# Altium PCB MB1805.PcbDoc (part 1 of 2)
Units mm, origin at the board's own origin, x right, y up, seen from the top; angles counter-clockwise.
Board outline 43 x 47.02 mm, 4 copper layers (Top Layer, Internal 1, Internal 2, Bottom Layer), stack 1.565 mm thick; 110 components, 91 nets, 377 pads, 610 vias.
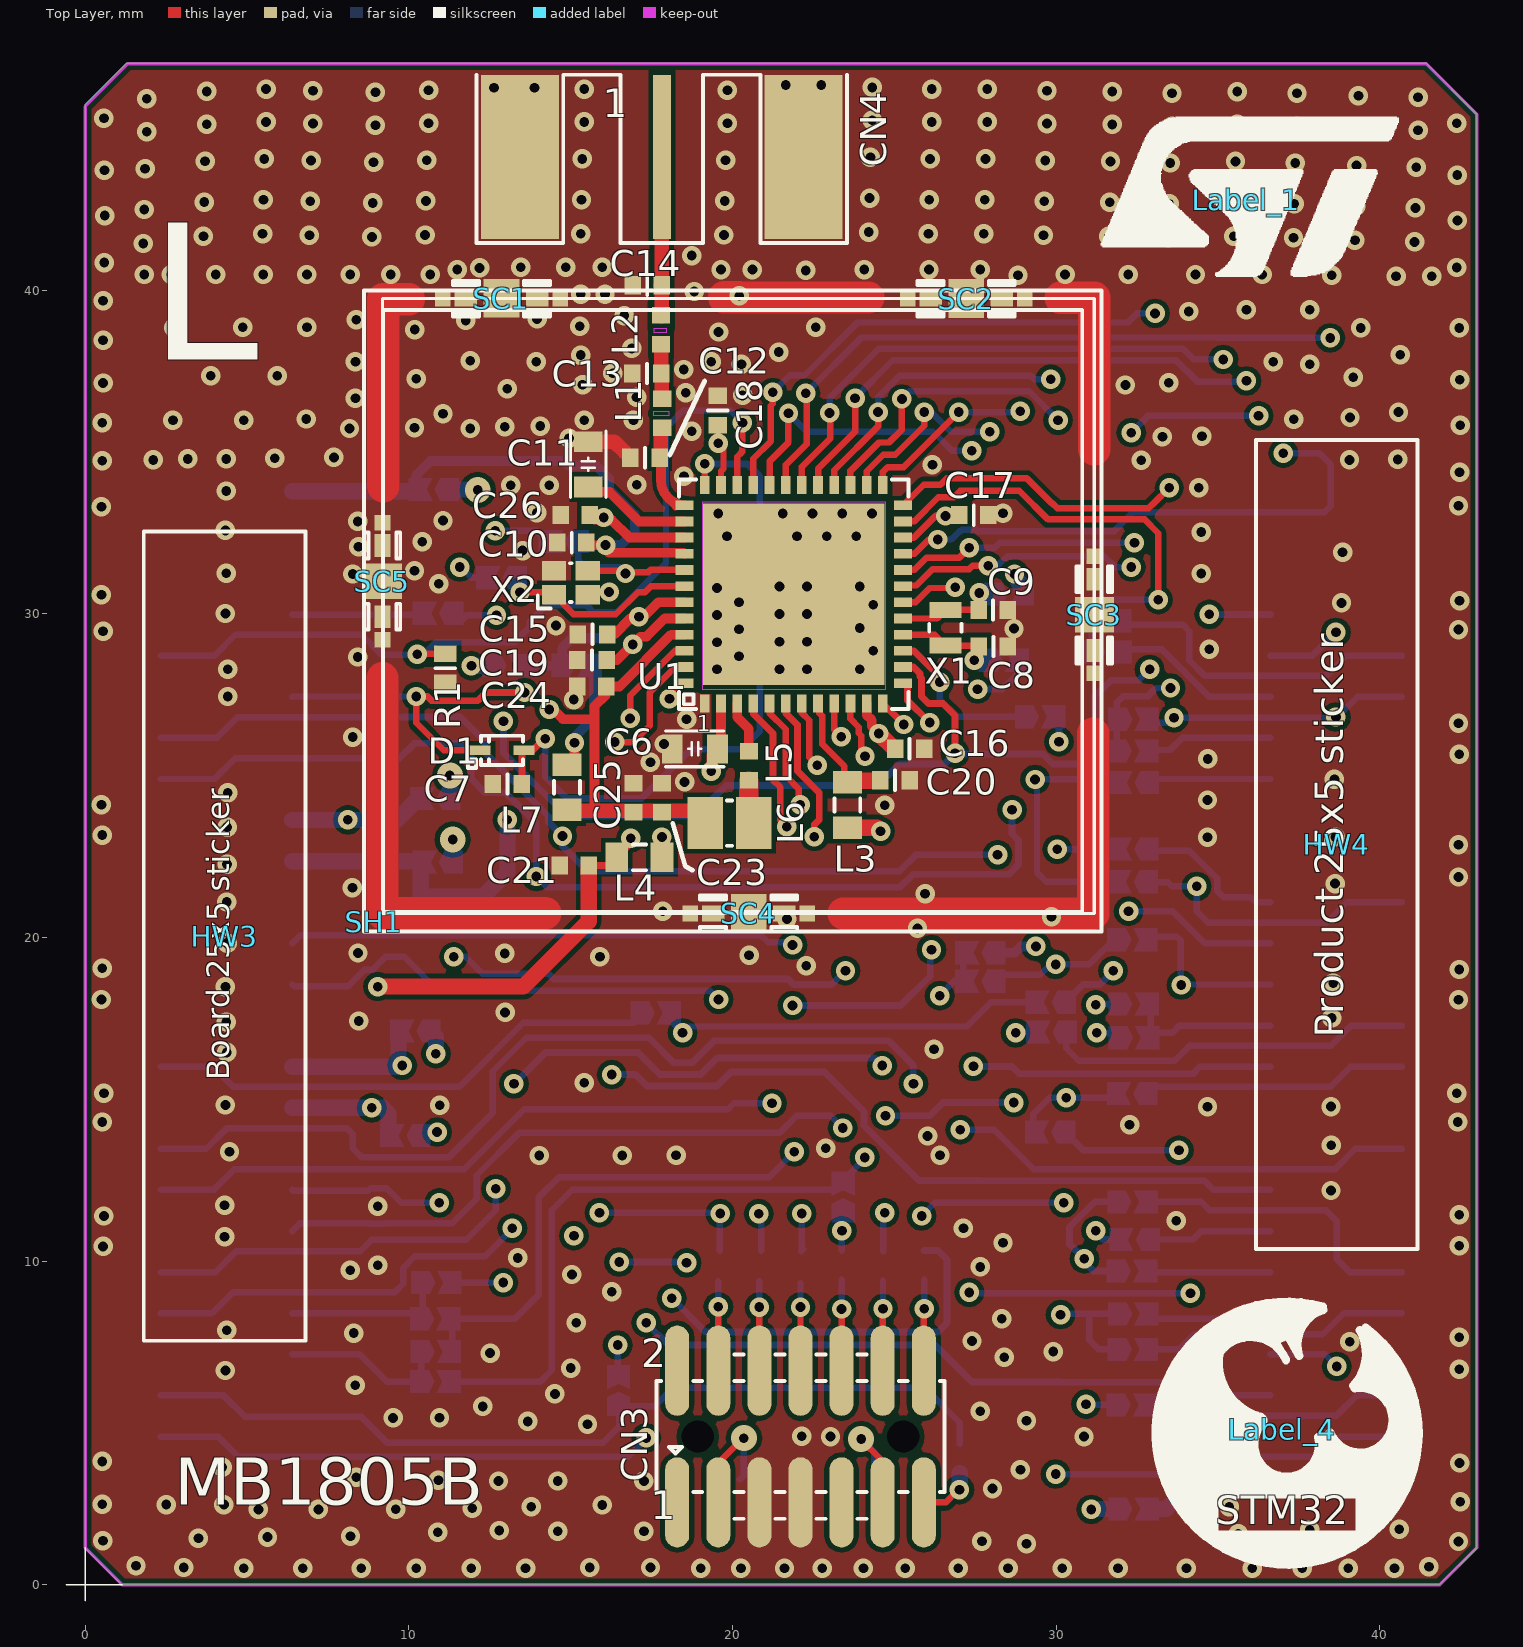
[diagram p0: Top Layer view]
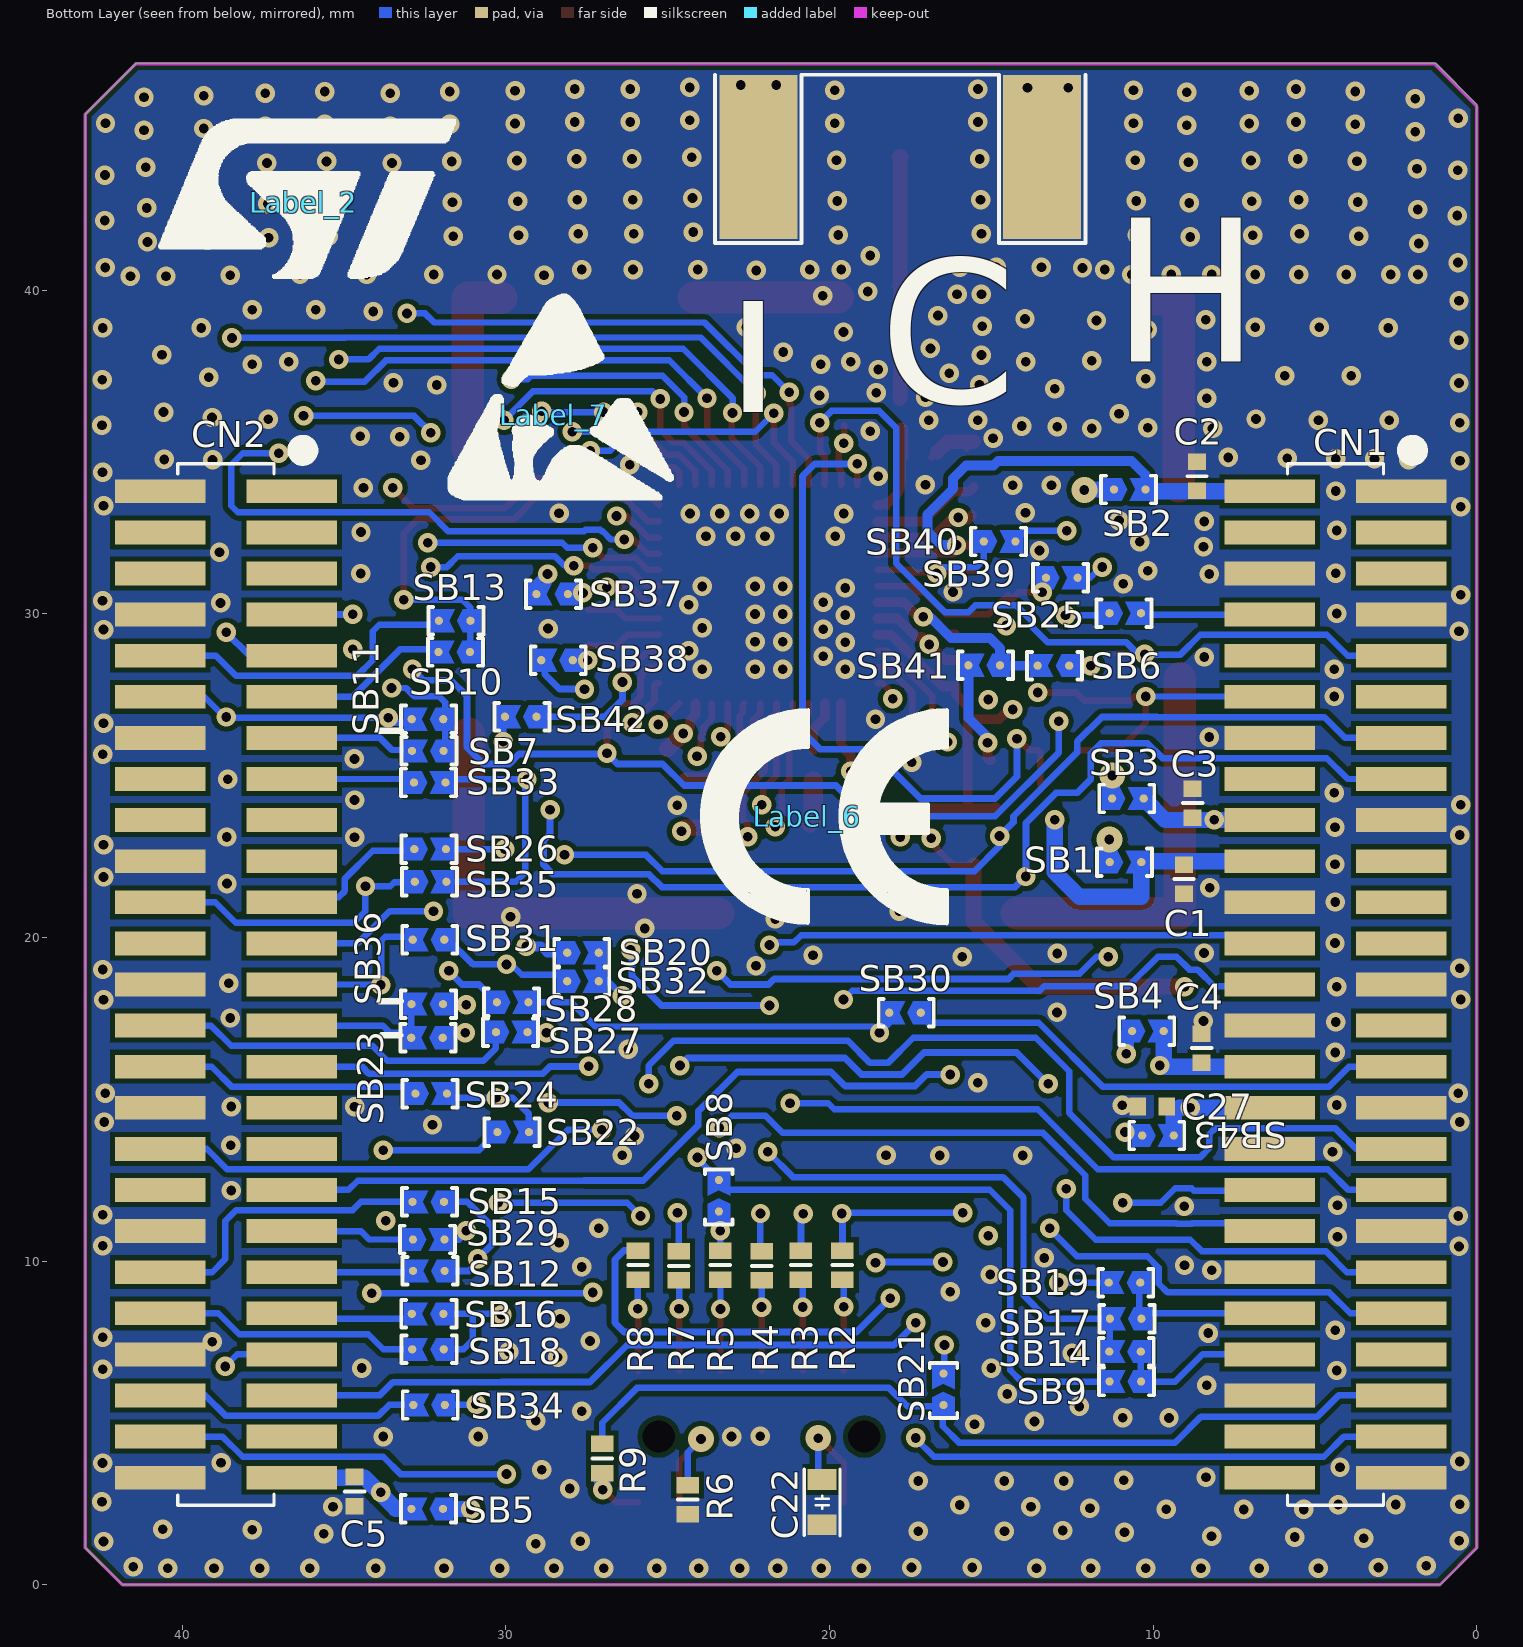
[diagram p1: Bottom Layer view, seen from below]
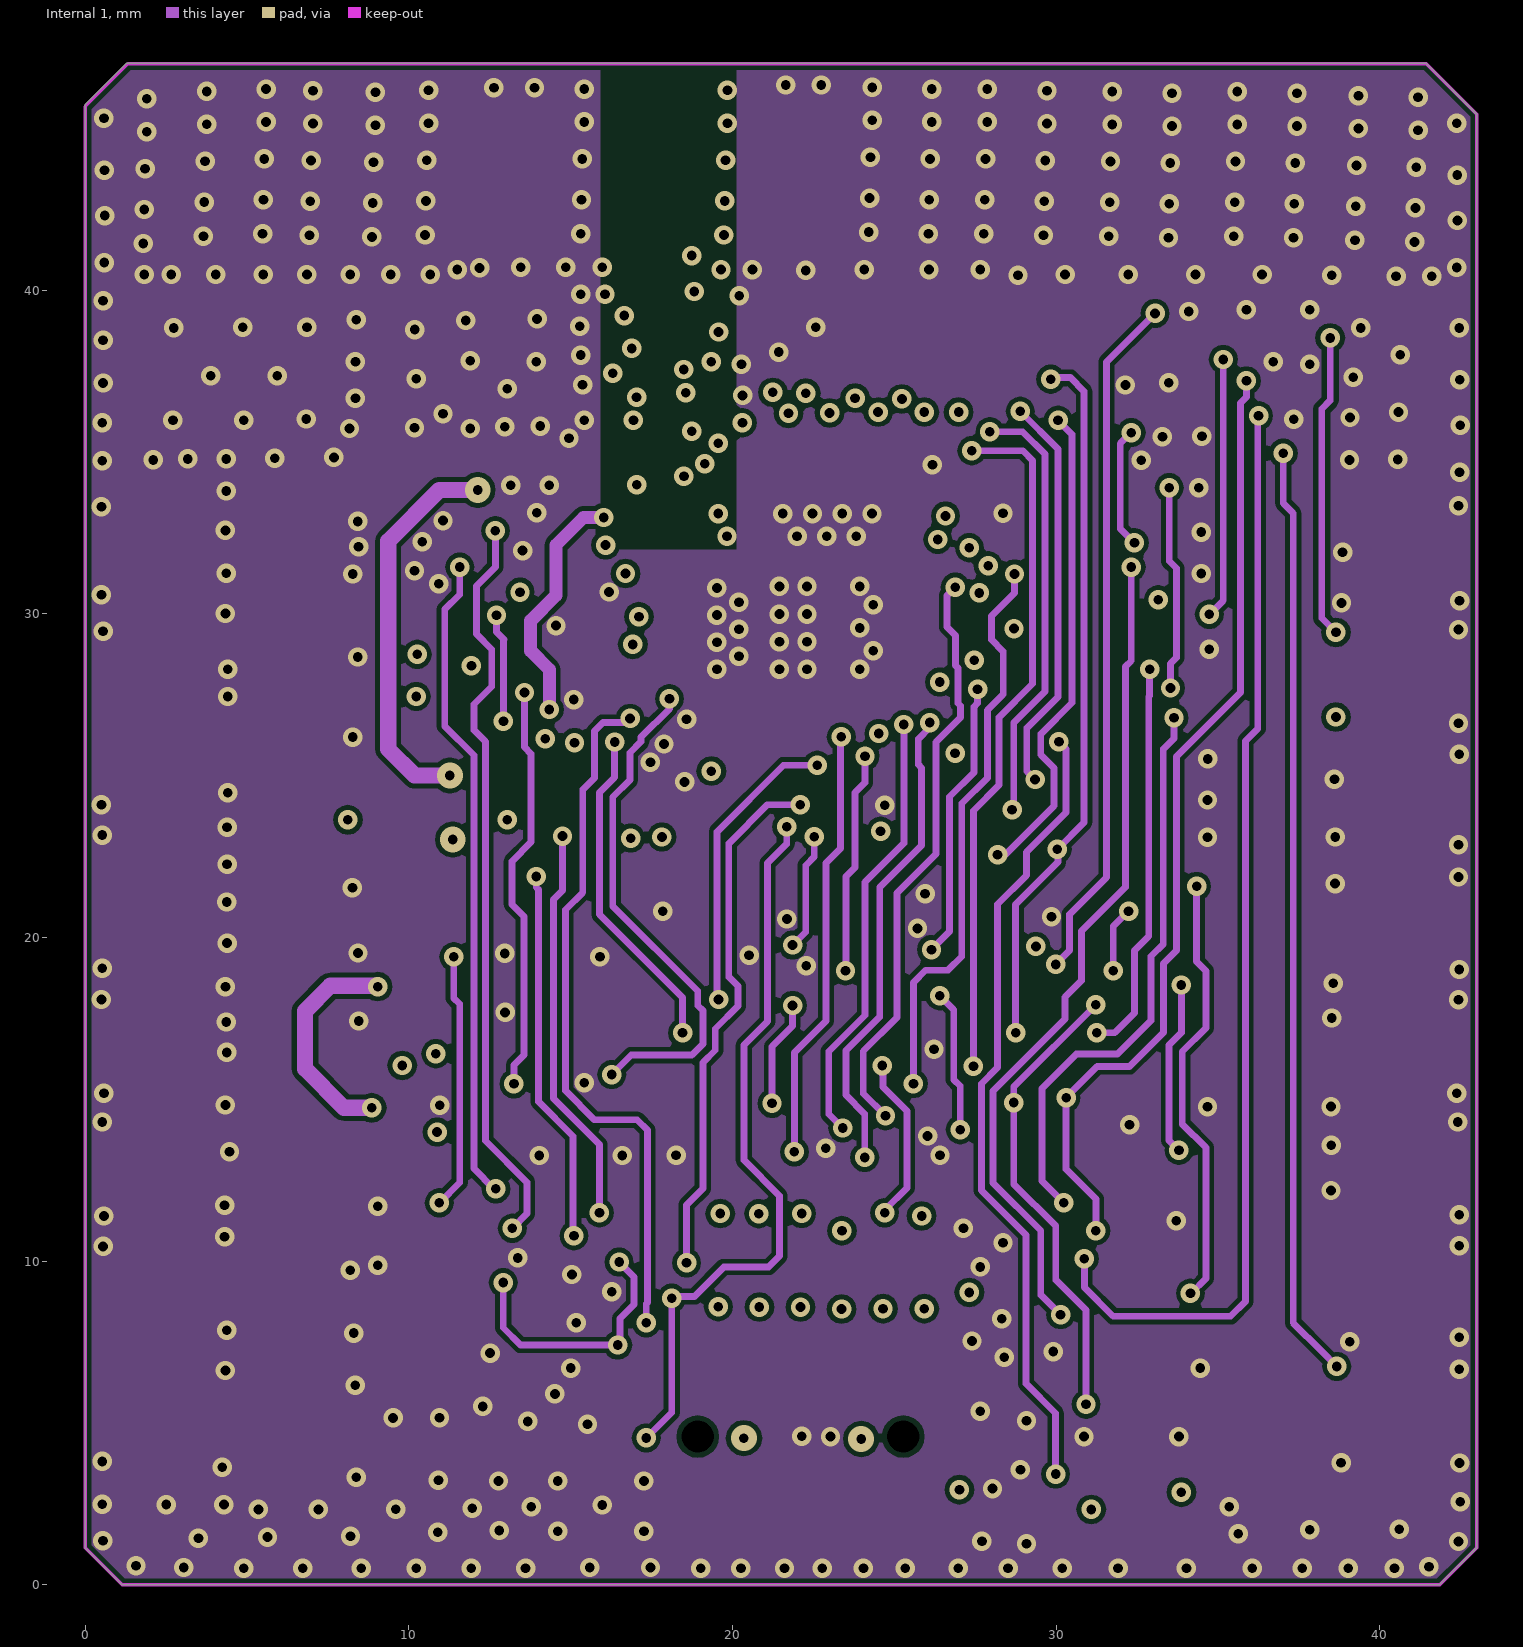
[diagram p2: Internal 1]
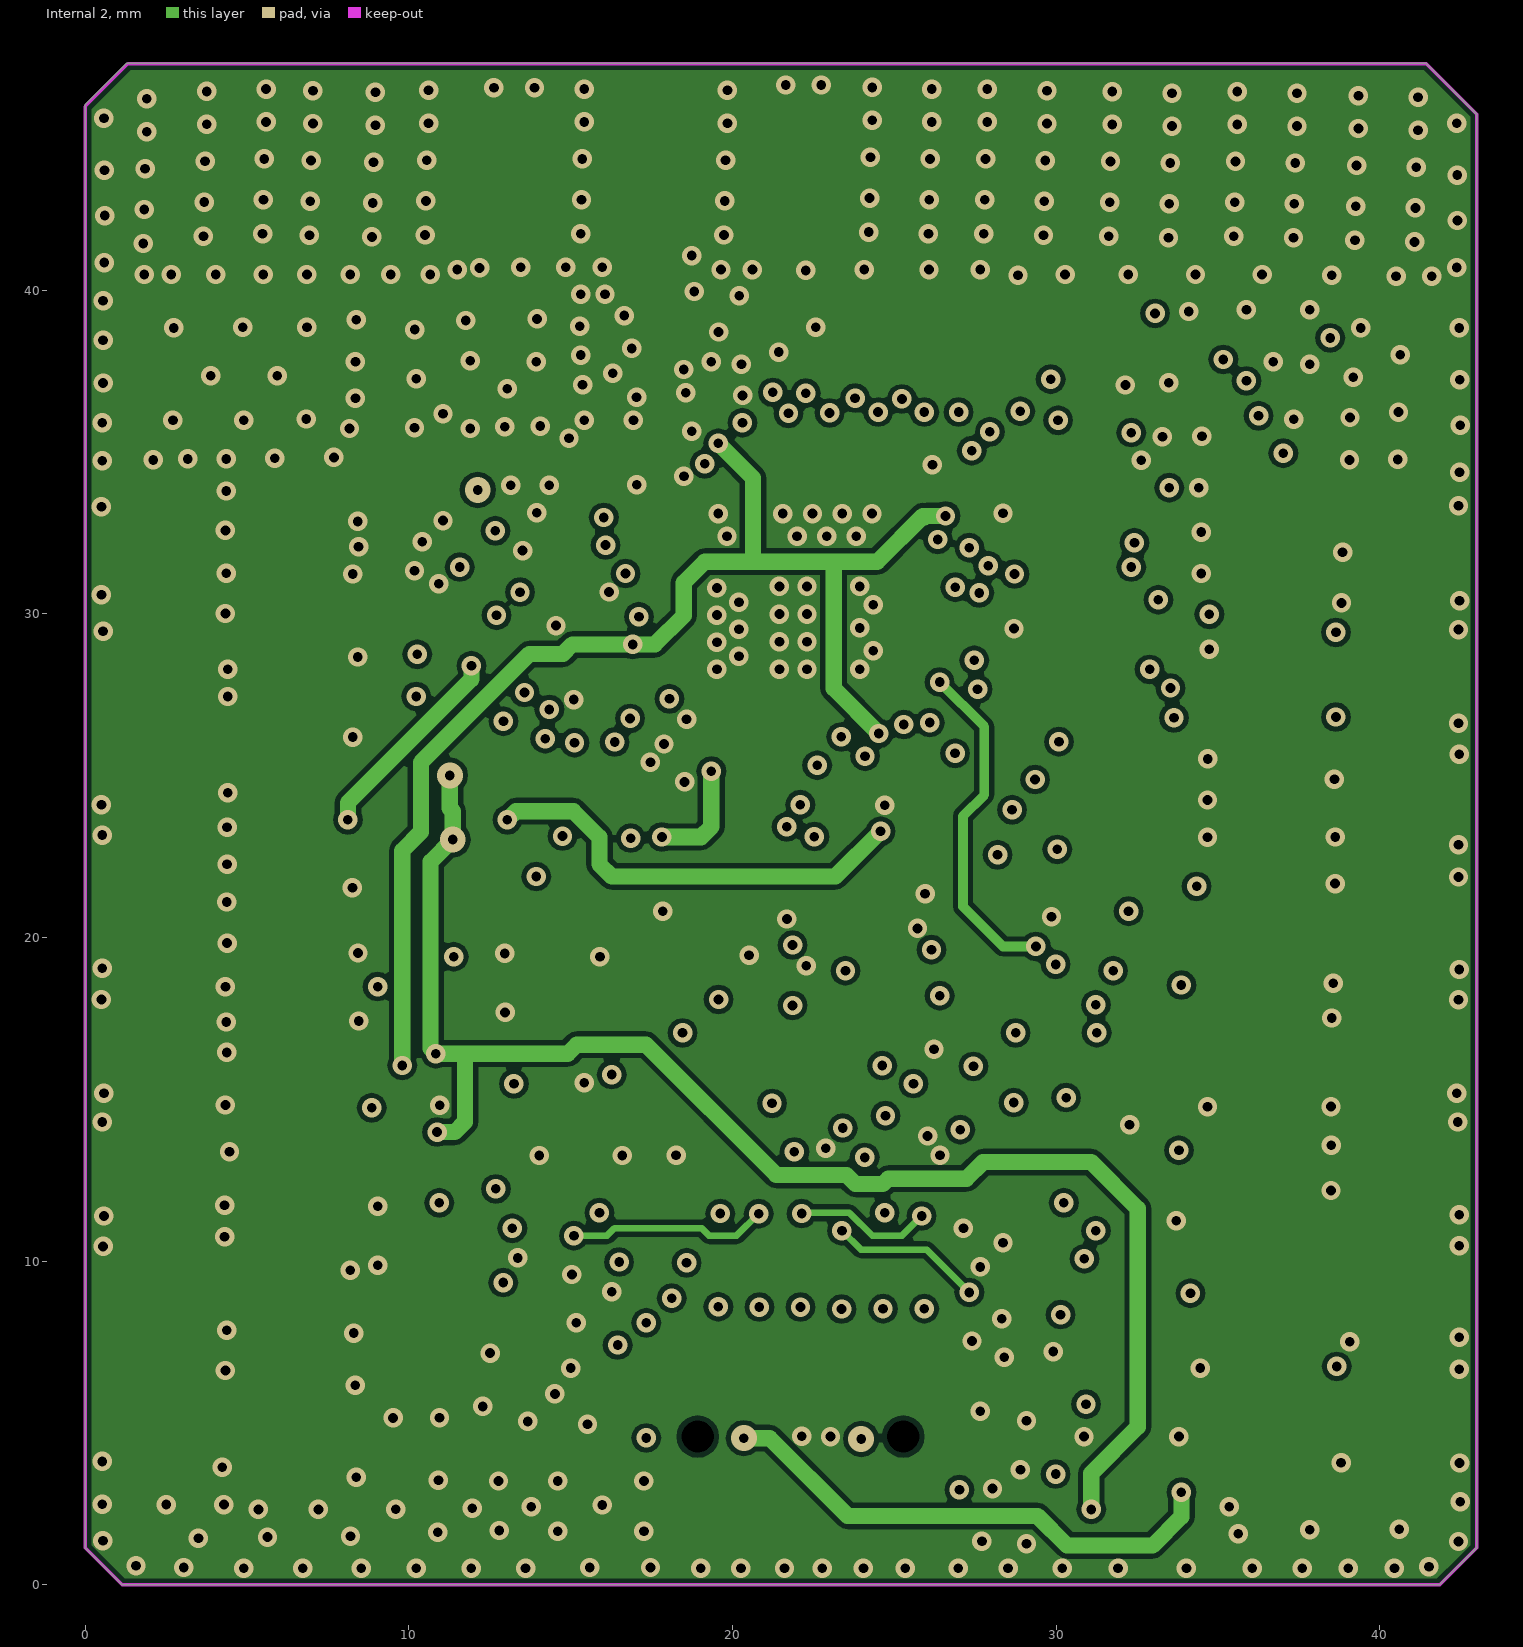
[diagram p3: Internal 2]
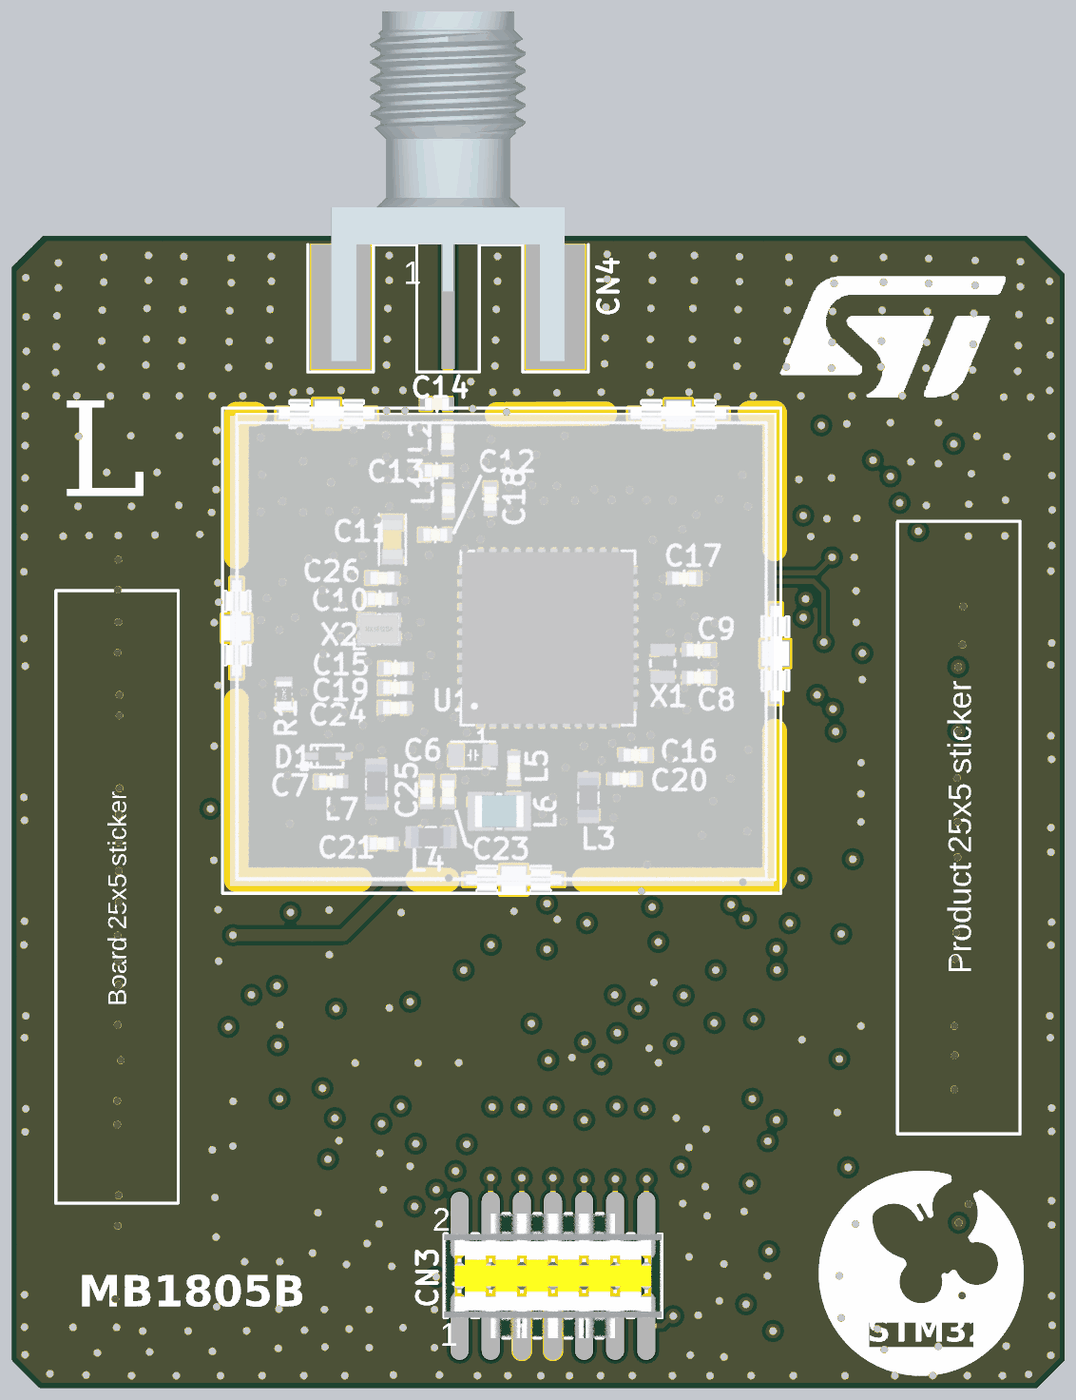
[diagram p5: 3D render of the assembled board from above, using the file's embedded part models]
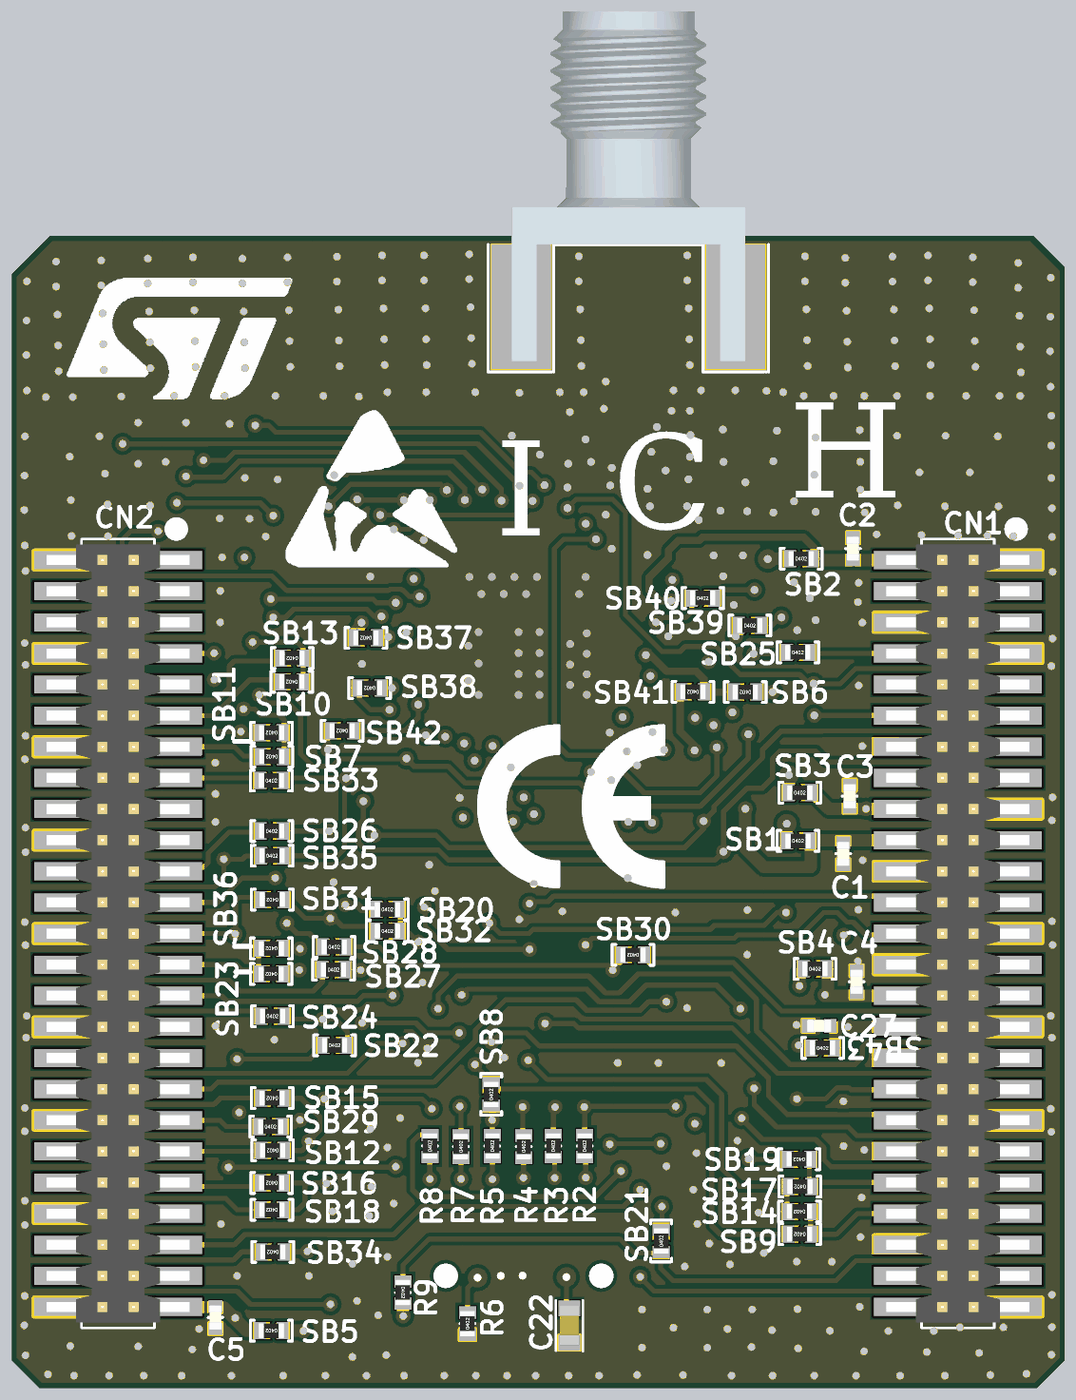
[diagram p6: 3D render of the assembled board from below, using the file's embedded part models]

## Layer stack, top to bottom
Top Solder: solder mask 0.0178, Solder Resist, Dk 4.2
Top Layer: signal copper 0.0406
Dielectric 1: core 0.0762, FR-4, Dk 3.7
Internal 1: signal copper 0.0305
Dielectric 3: prepreg 1.27, Dk 4.5
Internal 2: signal copper 0.0305
Dielectric 2: core 0.0762, Dk 3.7
Bottom Layer: signal copper 0.0406
Bottom Solder: solder mask 0.0178, Solder Resist, Dk 4.2

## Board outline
0,1.139 1.139,0 41.852,0 43.001,1.141 43,39.982 43,45.443 41.427,47.015 1.273,47.015 0.003,45.745 0,45.72

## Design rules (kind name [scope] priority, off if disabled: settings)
Clearance "RF Path 3" [InNet('NetC12_2')] p1: gap=0.13 ignorepadtopadclearanceinfootprint=FALSE
Clearance "RF Path 2" [InNet('NetC13_2')] p2: gap=0.13 ignorepadtopadclearanceinfootprint=FALSE
Clearance "RF Path 1" [InNet('ANT')] p3: gap=0.13 ignorepadtopadclearanceinfootprint=FALSE
Clearance [All] p4: gap=0.15 ignorepadtopadclearanceinfootprint=FALSE
ComponentClearance [All] p1: gap=0.2 collisioncheckmode=3 verticalgap=0.2 showdistances=FALSE
HoleSize [All] p1: absolutevalues=TRUE maxlimit=10 minlimit=0.025 maxpercent=80.000 minpercent=20.000
MinimumSolderMaskSliver [All] p1: minsoldermaskwidth=0.1
PlaneConnect [All] p1: planeconnectstyle=Relief reliefexpansion=0.508 reliefentries=4 reliefconductorwidth=0.21 reliefairgap=0.21
PolygonConnect Path_RF [InNet('NetC12_2')] p1: connectstyle=Direct reliefconductorwidth=0.254 reliefentries=4 polygonreliefangle="90 Angle" airgapwidth=0.254
PolygonConnect PolygonConnect_via [IsVia] p2: connectstyle=Direct reliefconductorwidth=0.254 reliefentries=4 polygonreliefangle="90 Angle" airgapwidth=0.254
PolygonConnect General [All] p3: connectstyle=Direct reliefconductorwidth=0.2 reliefentries=4 polygonreliefangle="90 Angle" airgapwidth=0.2
RoutingVias [All] p1: holewidth=0.3 width=0.8 viastyle="Through Hole" minholewidth=0.2 minwidth=0.5 maxholewidth=3.5 maxwidth=6.5
SilkToSilkClearance [All] p1 off: silktosilkclearance=0.2
SilkToSolderMaskClearance [IsPad] p1 off: minsilkscreentomaskgap=0.2 clearancetoexposedcopper=TRUE
SolderMaskExpansion [All] p1: expansion=0.102 istentingtop=FALSE
Width [All] p1: maxlimit=6 minlimit=0.15 preferedwidth=0.254 toplayer_prefwidth=0.2 midlayer1_minwidth=0.21 midlayer1_maxwidth=0.512 midlayer2_minwidth=0.21 midlayer2_maxwidth=0.512 bottomlayer_prefwidth=0.2 minimp=50.000000 maximp=50.000000 favimp=50.000000
24 further rules are at their usual default settings.

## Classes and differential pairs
component class "STM32 microcontroller I/Os & Clock": C1 C2 C3 C4 C5 C7 C8 C9 C27 CN1 CN2 D1 R1 SB1 SB2 SB3 SB4 SB5 SB7 SB8 SB9 SB10 SB11 SB12 SB13 SB14 SB15 SB16 SB17 SB18 SB19 SB20 SB21 SB22 SB23 SB24 SB25 SB26 SB27 SB28 SB29 SB30 SB31 SB32 SB33 SB34 SB35 SB36 SB37 SB38 SB39 SB40 SB42 SB43 U1 X1 X2
component class "RF & Power Management Schematic": C6 C10 C11 C12 C13 C14 C15 C16 C17 C18 C19 C20 C21 C22 C23 C24 C25 C26 CN3 CN4 L1 L2 L3 L4 L5 L6 L7 R2 R3 R4 R5 R6 R7 R8 R9 SB6 SB41 SC1 SC2 SC3 SC4 SC5 SH1
component class Project_Overview: HW2 HW3 HW4

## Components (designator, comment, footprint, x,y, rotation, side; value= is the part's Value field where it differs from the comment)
C1 "Capacitor" C0402 9.05,21.804 r90 bottom value=1uF
C2 "Capacitor" C0402 8.649,34.255 r270 bottom value=1uF
C3 "Capacitor" C0402 8.782,24.151 r270 bottom value=1uF
C4 "Capacitor" C0402 8.504,16.581 r270 bottom value=1uF
C5 "Capacitor" C0402 34.678,2.881 r90 bottom value=1uF
C6 "Capacitor" C0603_H0P8 18.837,25.829 r180 top value=10µF
C7 "Capacitor" C0402 13.042,24.745 r0 top value=100nF
C8 "Capacitor" C0402 28.061,28.996 r180 top value=6pF
C9 "Capacitor" C0402 28.053,30.119 r180 top value=6pF
C10 "Capacitor" C0402 15.034,32.202 r180 top value=100nF
C11 "Capacitor" C0603 15.545,34.62 r270 top value=470nF
C12 "Capacitor" C0402 17.297,34.823 r0 top value=1.5pF
C13 "Capacitor" C0402 17.355,37.43 r0 top value=1.8pF
C14 "Capacitor" C0402 17.366,40.157 r0 top value=1pF
C15 "Capacitor" C0402 15.673,29.369 r180 top value=100nF
C16 "Capacitor" C0402 25.474,25.831 r0 top value=100nF
C17 "Capacitor" C0402 27.457,33.052 r0 top value=100nF
C18 "Capacitor" C0402 19.546,36.287 r90 top value=100nF
C19 "Capacitor" C0402 15.658,28.575 r180 top value=100nF
C20 "Capacitor" C0402 25.02,24.861 r180 top value=1uF
C21 "Capacitor" C0402 15.107,22.221 r180 top value=1uF
C22 "Capacitor" C0603 20.231,2.554 r90 bottom value=1uF
C23 "Capacitor" C0402 17.825,24.314 r270 top value=4.7uF
C24 "Capacitor" C0402 15.652,27.759 r180 top value=100nF
C25 "Capacitor" C0402 16.941,24.323 r90 top value=2.2uF
C26 "Capacitor" C0402 15.138,33.057 r180 top value=100nF
C27 "Capacitor" C0402 10.029,14.782 r180 bottom value=1uF
CN1 "FTSH-125-02-L-DV" FTSH-125-02-L-DV 4.366,18.548 r180 bottom locked value="Header 25x2"
CN2 "FTSH-125-02-L-DV" FTSH-125-02-L-DV 38.656,18.548 r180 bottom locked value="Header 25x2"
CN3 "Header 7x2" CON_SAMTEC_FTSH-107-01-L-DV-K-A 22.101,4.579 r0 top
CN4 "mmcx" CON_SMA-RF_CINCH_142-0701-851 17.819,46.66 r0 top value=Jack_SMA_142-0701-851
D1 "SCHOTTKY_1A_2K" DIO_SOD523_1A_2K 12.879,25.784 r180 top value=BAT54KFILM
Designator14 "Comment" PCB_SPECIFICATIONS -3.124,121.133 r0 top
Designator15 "Comment" Sheetbox_4L2S 49.329,-12.006 r0 top
Designator16 "Comment" IMPEDANCE_TABLE -4.013,161.315 r0 top
HW3 "STICKER_BOARD" STICKER_BOARD_25X5 4.306,20.041 r90 top value="Sticker board"
HW4 "STICKER_PRODUCT" STICKER_PRODUCT_25X5 38.672,22.871 r90 top value="Sticker product"
L1 "Inductor" C0402 17.831,36.195 r90 top value=3.3nH
L2 "Inductor" C0402 17.796,38.776 r90 top value=3.3nH
L3 "Inductor" IND_0603_H0P8 23.549,24.094 r90 top value="47R @ 100MHz"
L4 "Inductor" IND_0603_H0P8 17.122,22.478 r180 top value="47R @ 100MHz"
L5 "Inductor" C0402 20.505,25.313 r270 top value=10nH
L6 "Inductor" L0805_H0P9 19.909,23.534 r180 top value=2.2uH
L7 "Inductor" IND_0603_H0P8 14.886,24.643 r270 top value="47R @ 100MHz"
Label_1 "LOGO_ST" LOGO_ST_Size3 35.882,42.799 r0 top
Label_2 "LOGO_ST" LOGO_ST_Size3 36.256,42.722 r180 bottom
Label_4 "LOGO_STM32" LOGO_STM32 36.982,4.801 r0 top
Label_6 "LOGO_CE" "LOGO CE" 20.684,23.741 r180 bottom
Label_7 "LOGO_ESD" "LOGO ESD" 28.525,36.153 r180 bottom
R1 "Resistor" R0402 11.125,28.32 r270 top value=100K
R2 "Resistor" R0402 19.605,9.878 r90 bottom value=47R
R3 "Resistor" R0402 20.887,9.878 r90 bottom value=47R
R4 "Resistor" R0402 22.092,9.852 r90 bottom value=47R
R5 "Resistor" R0402 23.376,9.878 r90 bottom value=47R
R6 "Resistor" R0402 24.386,2.631 r90 bottom value=47R
R7 "Resistor" R0402 24.658,9.853 r90 bottom value=47R
R8 "Resistor" R0402 25.922,9.878 r90 bottom value=47R
R9 "Resistor" R0402 27.024,3.9 r270 bottom value=47R
SB1 "SB_OFF" SOLDER-BRIDGE_R0402-0R 10.893,22.329 r180 bottom
SB2 "SB_OFF" SOLDER-BRIDGE_R0402-0R 10.764,33.846 r180 bottom
SB3 "SB_OFF" SOLDER-BRIDGE_R0402-0R 10.819,24.295 r180 bottom
SB4 "SB_OFF" SOLDER-BRIDGE_R0402-0R 10.201,17.107 r180 bottom
SB5 "SB_OFF" SOLDER-BRIDGE_R0402-0R 32.397,2.343 r0 bottom
SB6 "SB_OFF" SOLDER-BRIDGE_R0402-0R 13.046,28.401 r0 bottom
SB7 "SB_ON" SOLDER-BRIDGE_R0402-0R 32.378,25.767 r0 bottom
SB8 "SB_OFF" SOLDER-BRIDGE_R0402-0R 23.421,11.984 r90 bottom
SB9 "SB_ON" SOLDER-BRIDGE_R0402-0R 10.825,6.28 r0 bottom
SB10 "SB_ON" SOLDER-BRIDGE_R0402-0R 31.563,28.823 r0 bottom
SB11 "SB_ON" SOLDER-BRIDGE_R0402-0R 32.389,26.746 r0 bottom
SB12 "SB_ON" SOLDER-BRIDGE_R0402-0R 32.347,9.698 r0 bottom
SB13 "SB_ON" SOLDER-BRIDGE_R0402-0R 31.548,29.789 r0 bottom
SB14 "SB_OFF" SOLDER-BRIDGE_R0402-0R 10.834,7.205 r0 bottom
SB15 "SB_ON" SOLDER-BRIDGE_R0402-0R 32.364,11.832 r0 bottom
SB16 "SB_ON" SOLDER-BRIDGE_R0402-0R 32.385,8.371 r0 bottom
SB17 "SB_ON" SOLDER-BRIDGE_R0402-0R 10.814,8.221 r0 bottom
SB18 "SB_ON" SOLDER-BRIDGE_R0402-0R 32.373,7.274 r0 bottom
SB19 "SB_OFF" SOLDER-BRIDGE_R0402-0R 10.85,9.337 r0 bottom
SB20 "SB_OFF" SOLDER-BRIDGE_R0402-0R 27.658,19.531 r180 bottom
SB21 "SB_ON" SOLDER-BRIDGE_R0402-0R 16.481,6.002 r90 bottom
SB22 "SB_OFF" SOLDER-BRIDGE_R0402-0R 29.816,13.988 r180 bottom
SB23 "SB_ON" SOLDER-BRIDGE_R0402-0R 32.405,16.901 r0 bottom
SB24 "SB_ON" SOLDER-BRIDGE_R0402-0R 32.35,15.176 r180 bottom
SB25 "SB_OFF" SOLDER-BRIDGE_R0402-0R 10.902,30.022 r180 bottom
SB26 "SB_ON" SOLDER-BRIDGE_R0402-0R 32.383,22.731 r180 bottom
SB27 "SB_OFF" SOLDER-BRIDGE_R0402-0R 29.86,17.075 r180 bottom
SB28 "SB_OFF" SOLDER-BRIDGE_R0402-0R 29.832,18 r180 bottom
SB29 "SB_ON" SOLDER-BRIDGE_R0402-0R 32.427,10.668 r180 bottom
SB30 "SB_ON" SOLDER-BRIDGE_R0402-0R 17.632,17.676 r0 bottom
SB31 "SB_ON" SOLDER-BRIDGE_R0402-0R 32.357,19.932 r0 bottom
SB32 "SB_OFF" SOLDER-BRIDGE_R0402-0R 27.658,18.65 r180 bottom
SB33 "SB_ON" SOLDER-BRIDGE_R0402-0R 32.394,24.789 r180 bottom
SB34 "SB_ON" SOLDER-BRIDGE_R0402-0R 32.34,5.556 r0 bottom
SB35 "SB_OFF" SOLDER-BRIDGE_R0402-0R 32.367,21.723 r180 bottom
SB36 "SB_OFF" SOLDER-BRIDGE_R0402-0R 32.396,17.941 r0 bottom
SB37 "SB_OFF" SOLDER-BRIDGE_R0402-0R 28.537,30.612 r0 bottom
SB38 "SB_OFF" SOLDER-BRIDGE_R0402-0R 28.386,28.569 r0 bottom
SB39 "SB_OFF" SOLDER-BRIDGE_R0402-0R 12.862,31.117 r180 bottom
SB40 "SB_OFF" SOLDER-BRIDGE_R0402-0R 14.785,32.238 r180 bottom
SB41 "SB_ON" SOLDER-BRIDGE_R0402-0R 15.186,28.411 r0 bottom
SB42 "SB_ON" SOLDER-BRIDGE_R0402-0R 29.508,26.823 r0 bottom
SB43 "SB_OFF" SOLDER-BRIDGE_R0402-0R 9.891,13.88 r180 bottom
SC1 "Shield-clip_S0951-46R" CLIP_HARWIN_S0951-46R#1 12.862,39.742 r180 top value=S0951-46R
SC2 "Shield-clip_S0951-46R" CLIP_HARWIN_S0951-46R#2 27.222,39.742 r180 top value=S0951-46R
SC3 "Shield-clip_S0951-46R" CLIP_HARWIN_S0951-46R#2 31.182,29.971 r90 top value=S0951-46R
SC4 "Shield-clip_S0951-46R" CLIP_HARWIN_S0951-46R#2 20.502,20.745 r180 top value=S0951-46R
SC5 "Shield-clip_S0951-46R" CLIP_HARWIN_S0951-46R#2 9.185,31.013 r90 top value=S0951-46R
SH1 "RF Shield (22.2x19.2x2mm)" SHIELD_RF_ST-CUSTOM_22P2X19P2_H2 8.909,20.488 r0 top
U1 "STM32WBA55CGU6" ICC_UFQFPN48-EPAD_7X7_H0P55_P050 21.895,30.608 r90 top locked
X1 "XTAL_2_PINS" CRY_NX1610SE_2P 26.581,29.572 r270 top value=32.768kHz
X2 "XTAL_4_PINS" CRY_NX1612SA_4P 15.006,30.964 r0 top value=32MHz

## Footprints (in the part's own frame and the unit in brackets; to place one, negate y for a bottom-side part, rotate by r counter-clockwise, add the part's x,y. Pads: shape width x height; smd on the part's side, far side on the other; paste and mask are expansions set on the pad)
C0402 [mm]
  rect 0.51x0.56 smd mask+0.05: 1(-0.45,0) 2(0.45,0)
  silkscreen extent 0,-0.3 0,0.3, body extent -0.5,-0.3 0.5,0.3, height 0.4
C0603 [mm]
  rect 0.64x0.89 smd mask+0.05: 1(-0.7,0) 2(0.7,0)
  silkscreen extent -1.05,-0.55 1.02,0.55, body extent -0.9,-0.5 0.9,0.5, height 1.4
C0603_H0P8 [mm] "MCD-01540"
  rect 0.64x0.89 smd mask+0.05: 1(-0.7,0) 2(0.7,0)
  silkscreen extent -0.9,-0.55 0.9,0.55, body extent -0.9,-0.5 0.9,0.5, height 1
CLIP_HARWIN_S0951-46R#1 [mm] "MCD-01587_CLIP-X1"
  rect 0.48x0.5 smd mask+0.1: 1(-1.81,0) 1(1.81,0)
  rect 0.7x0.5 smd mask+0.1: 1(-1.1,0) 1(1.1,0)
  rect 1.1x1.2 smd mask+0.1: 1(0,-0.013)
  silkscreen extent -1.5,-0.55 1.5,0.55, body extent -2.05,-0.65 2.05,0.65, height 1.28
CLIP_HARWIN_S0951-46R#2 [mm] "MCD-01587_CLIP-X1"
  rect 0.48x0.5 smd mask+0.1: 1(-1.81,0) 1(1.81,0)
  rect 0.7x0.5 smd mask+0.1: 1(-1.1,0) 1(1.1,0)
  rect 1.1x1.2 smd mask+0.1: 1(0,0)
  silkscreen extent -1.5,-0.55 1.5,0.55, body extent -2.05,-0.65 2.05,0.65, height 1.28
CON_SAMTEC_FTSH-107-01-L-DV-K-A [mm] "MCD-01959"
  oval 0.74x2.79 smd mask+0.05: 1(-3.81,-2.035) 2(-3.81,2.035) 3(-2.54,-2.035) 4(-2.54,2.035) 5(-1.27,-2.035) 6(-1.27,2.035) 7(0,-2.035) 8(0,2.035) 9(1.27,-2.035) 10(1.27,2.035) 11(2.54,-2.035) 12(2.54,2.035) 13(3.81,-2.035) 14(3.81,2.035)
  round 0 hole 1 unplated paste-10 mask+0.05: NPTH1(-3.175,0) NPTH2(3.175,0)
  silkscreen extent -4.44,-2.54 4.44,2.54, body extent -4.44,-2.92 4.45,2.92, height 6.12
CON_SMA-RF_CINCH_142-0701-851 [mil] "MCD-02072"
  rect 21.65x200 smd mask+1.97: 1(0,-100)
  rect 95x200 smd mask+1.97: 2(172.48,-100) 3(-172.48,-100)
  rect 95x200 smd far side mask+1.97: 4(-172.48,-100) 5(172.48,-100)
  silkscreen extent -225,-205 225,0, body extent -189,-187 189,376, height 161
CRY_NX1610SE_2P [mm] "MCD-02291"
  rect 0.5x1 smd mask+0.05: 1(-0.55,0) 2(0.55,0)
  silkscreen extent -0.13,-0.5 0.13,0.5, body extent -0.8,-0.5 0.8,0.5, height 0.45
CRY_NX1612SA_4P [mm] "MCD-02262"
  rect 0.75x0.6 smd mask+0.038: 1(-0.525,-0.375) 2(0.525,-0.375) 3(0.525,0.375) 4(-0.525,0.375)
  silkscreen extent -1.02,-0.8 0.03,0.6, body extent -0.8,-0.6 0.8,0.6, height 0.51
DIO_SOD523_1A_2K [mm] "MCD-01677"
  rect 0.65x0.3 smd mask+0.05: 1(-0.675,0) 2(0.675,0)
  silkscreen extent -0.65,-0.45 1.05,0.55, body extent -0.85,-0.45 0.85,0.45, height 0.71
FTSH-125-02-L-DV [mil] "Header2x25 Reverse 1.27mm SAMTEC (FTSH-125-02-L-DV)"
  rect 110x29.02 smd: 1(80,600) 2(-80,600) 3(80,550) 4(-80,550) 5(80,500) 6(-80,500) 7(80,450) 8(-80,450) 9(80,400) 10(-80,400) 11(80,350) 12(-80,350) 13(80,300) 14(-80,300) 15(80,250) 16(-80,250) 17(80,200) 18(-80,200) 19(80,150) 20(-80,150) 21(80,100) 22(-80,100) 23(80,50) 24(-80,50) 25(80,0) 26(-80,0) 27(80,-50) 28(-80,-50) 29(80,-100) 30(-80,-100) 31(80,-150) 32(-80,-150) 33(80,-200) 34(-80,-200) 35(80,-250) 36(-80,-250) 37(80,-300) 38(-80,-300) 39(80,-350) 40(-80,-350) 41(80,-400) 42(-80,-400) 43(80,-450) 44(-80,-450) 45(80,-500) 46(-80,-500) 47(80,-550) 48(-80,-550) 49(80,-600) 50(-80,-600)
  silkscreen extent -58,-633 103,659, body extent -115,-625 115,625, height 190
ICC_UFQFPN48-EPAD_7X7_H0P55_P050 [mm] "MCD-01704"
  rect 0.55x0.3 smd mask+0.05: 1(-3.375,2.75) 2(-3.375,2.25) 3(-3.375,1.75) 4(-3.375,1.25) 5(-3.375,0.75) 6(-3.375,0.25) 7(-3.375,-0.25) 8(-3.375,-0.75) 9(-3.375,-1.25) 10(-3.375,-1.75) 11(-3.375,-2.25) 12(-3.375,-2.75) 25(3.375,-2.75) 26(3.375,-2.25) 27(3.375,-1.75) 28(3.375,-1.25) 29(3.375,-0.75) 30(3.375,-0.25) 31(3.375,0.25) 32(3.375,0.75) 33(3.375,1.25) 34(3.375,1.75) 35(3.375,2.25) 36(3.375,2.75)
  rect 0.3x0.55 smd mask+0.05: 13(-2.75,-3.375) 14(-2.25,-3.375) 15(-1.75,-3.375) 16(-1.25,-3.375) 17(-0.75,-3.375) 18(-0.25,-3.375) 19(0.25,-3.375) 20(0.75,-3.375) 21(1.25,-3.375) 22(1.75,-3.375) 23(2.25,-3.375) 24(2.75,-3.375) 37(2.75,3.375) 38(2.25,3.375) 39(1.75,3.375) 40(1.25,3.375) 41(0.75,3.375) 42(0.25,3.375) 43(-0.25,3.375) 44(-0.75,3.375) 45(-1.25,3.375) 46(-1.75,3.375) 47(-2.25,3.375) 48(-2.75,3.375)
  rect 5.6x5.6 smd mask+0.05: 49(0,0)
  silkscreen extent -3.55,-3.55 3.55,3.55, body extent -3.5,-3.5 3.5,3.5, height 0.65
IMPEDANCE_TABLE [mm]
IND_0603_H0P8 [mm]
  rect 0.7x0.9 smd mask+0.05: 1(-0.7,0) 2(0.7,0)
  silkscreen extent -0.2,-0.4 0.2,0.4, body extent -0.8,-0.4 0.8,0.4, height 0.8
L0805_H0P9 [mm]
  rect 1.1x1.6 smd mask+0.05: 1(-0.75,0) 2(0.75,0)
  silkscreen extent -0.08,-0.7 0.08,0.7, body extent -1.07,-0.7 1.07,0.7, height 1.2
"LOGO CE" [mm]
  silkscreen extent -3.27,-3.31 4.33,3.3
"LOGO ESD" [mm]
  silkscreen extent -3.23,-2.59 3.66,3.68
LOGO_ST_Size3 [mm]
  silkscreen extent -4.5,-2.36 4.7,2.57
LOGO_STM32 [mm]
  silkscreen extent -3.9,-4.23 4.33,3.95
PCB_SPECIFICATIONS [mm]
R0402 [mm]
  rect 0.51x0.7 smd mask+0.05: 1(-0.45,0) 2(0.45,0)
  silkscreen extent 0,-0.3 0,0.3, body extent -0.52,-0.3 0.52,0.3, height 0.4
Sheetbox_4L2S [mil] "Sheetbox 4 layers / 2 silkscreens"
  round 20 on Mech16: 1(813.78,210.69) 1(2736.9,210.69)
SHIELD_RF_ST-CUSTOM_22P2X19P2_H2 [mm] "MCD-02088"
  silkscreen extent -0.3,-0.3 22.5,19.5, body extent 0,0 22.2,19.2, height 2.45
SOLDER-BRIDGE_R0402-0R [mil] "MCD-01619"
  round 10 smd paste-393.7: 1(-17.72,0) 2(20.67,0)
  Top Layer region: -30.51,-13.78 -30.51,13.78 -8.37,13.78 -1.48,0 -8.37,-13.78
  Top Layer region: 1.48,13.78 8.37,0 1.48,-13.78 30.51,-13.78 30.51,13.78
  silkscreen extent -33,-17 33,17, body extent -20,-12 20,12, height 14
STICKER_BOARD_25X5 [mm] "Sticker to mention board reference + serial number"
  silkscreen extent -12.5,-2.5 12.5,2.5, body extent -12.5,-2.5 12.5,2.5, height 0.01
STICKER_PRODUCT_25X5 [mm] "Sticker to mention board CPN code"
  silkscreen extent -12.5,-2.5 12.5,2.5

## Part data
C1 C2 C3 C4 C5 C20 C21 C27: library part MCD-01722, "Capacitor, MLCC, 1uF, 10V, X5R, +/-10%, 0402, T=0.5mm", Manufacturer=YAGEO, Manufacturer_Part_Number=CC0402KRX5R6BB105, Package=0402
C6: library part MCD-02733, "Capacitor, MLCC, 10uF, 10V, X6S, +/-20%, 0603, T=1mm", Manufacturer=MURATA, Manufacturer_Part_Number=GRM188C81A106MA73, Package=0603
C7 C10 C15 C16 C17 C18 C19 C24 C26: library part MCD-00006, "Capacitor, MLCC, 100nF, 16V, X7R, +/-10%, 0402, T=0.5mm", Alternate_Manufacturer=MURATA, Alternate_Manufacturer_Part_Number=GCM155R71C104KA55D, Manufacturer=YAGEO, Manufacturer_Part_Number=CC0402KRX7R7BB104, Package=C0402
C8 C9: library part MCD-03185, "Capacitor, MLCC, 6 pF, 50V, NPO, ±0,25pF, 0402, T=0.5mm", Manufacturer=MURATA, Manufacturer_Part_Number=GJM1555C1H6R0CB01, Package=0402
C11: library part MCD-01006, "Capacitor, MLCC, 470nF, 16V, X7R, +/-10%, 0603, T=0.8mm", Manufacturer=YAGEO, Manufacturer_Part_Number=CC0603KRX7R7BB474, Package=0603
C12: library part MCD-02994, "Capacitor, MLCC, 1.5pF, 50V, C0G, +/-0.25pF, 0402, T=0.5mm", Manufacturer=MURATA, Manufacturer_Part_Number=GRM1555C1H1R5CA01, Package=0402
C13: library part MCD-02995, "Capacitor, MLCC, 1.8pF, 50V, C0G, +/-0.25pF, 0402, T=0.5mm", Manufacturer=MURATA, Manufacturer_Part_Number=GRM1555C1H1R8CA01, Package=0402
C14: library part MCD-03045, "Capacitor, MLCC, 1.0pF, 50V, C0G, +/-0.25pF, 0402, T=0.5mm", Manufacturer=MURATA, Manufacturer_Part_Number=GRM1555C1H1R0CA01, Package=0402
C22: library part MCD-00010, "Capacitor, MLCC, 1uF, 16V, X5R, 10%, 0603, T=0,8mm", Manufacturer=YAGEO, Manufacturer_Part_Number=CC0603KRX5R7BB105, Package=C0603
C23: library part MCD-01356, "Capacitor, MLCC, 4.7uF, 6V3, X5R, +/-20%, 0402, T=0.5mm", Manufacturer=MURATA, Manufacturer_Part_Number=GRM155R60J475ME47, Package=0402
C25: library part MCD-01823, "Capacitor, MLCC, 2.2uF, 6V3, X5R,+/-10%, 0402, T=0.5mm", Manufacturer=MURATA, Manufacturer_Part_Number=GRM155R60J225KE95D, Package=0402
CN1 CN2: library part MCD-02746, "Header, 25x2, 12.7mm, VR, SMD, T=4.83mm", Manufacturer=SAMTEC
CN3: library part MCD-01531, "Header, 7x2, 1.27mm, VR, T=5.97mm, FTSH series STDC14 without Alignment Pin", Manufacturer=SAMTEC, Manufacturer_Part_Number=FTSH-107-01-L-DV-K
CN4: library part MCD-02072, "Jack_SMA, VR, PCB edge, 50R, T=7.92mm", Alternate_Manufacturer=N/A, Manufacturer=CINCH, Manufacturer_Part_Number=142-0701-851
D1: library part MCD-01677, "Small signal Schottky diodes", Manufacturer=STMICROELECTRONICS, Manufacturer_HQ_COO=EU, Manufacturer_Part_Number=BAT54KFILM, Package=SOD-523
Designator14 Designator15 Designator16: library part MCD-00279
HW3: library part MCD-02190, "Sticker board 25x5 mm", Alternate_Manufacturer=N/A
HW4: library part MCD-02189, "Sticker product 25x5 mm", Alternate_Manufacturer=N/A
L1 L2: library part MCD-03001, "Inductor, 3.3nH, +/-0.3nH, 0.8A,125mR, 0402, T=0.5mm", Manufacturer=MURATA, Manufacturer_Part_Number=LQG15HS3N3S02, Package=0402
L3: library part MCD-02587, "Ferrite bead, 47R @ 100MHz, +/-25%, 3.5A, 0R02, 0603, T=0.8mm", Manufacturer="TAIYO YUDEN", Manufacturer_Part_Number=FBMH1608HM470-T, Package=0603
L4 L7: library part MCD-02587, "Ferrite bead, 47R @ 100MHz, +/-25%, 3.5A, 0R02, 0603, T=0.8mm", Alternate_Manufacturer=N/A, Manufacturer="TAIYO YUDEN", Manufacturer_Part_Number=FBMH1608HM470-T, Package=0603
L5: library part MCD-03035, "Inductor, 10nH, +/-2%, 500 mA, 0.26Ohm, 0402, T=0.5mm", Manufacturer=MURATA, Manufacturer_Part_Number=LQG15HS10NJ02D, Package=0402
L6: library part MCD-01060, "Inductor, 2.2uH, +/-20%, 0.7A, 0R156, 0805, T=0.9mm", Alternate_Manufacturer=N/A, Manufacturer=MURATA, Manufacturer_Part_Number=LQM21PN2R2MGH, Package=0805
R1: library part MCD-00059, "Resistor, 100K, 0402, +/-1%, 1/16W", Manufacturer=YAGEO, Manufacturer_Part_Number=RC0402FR-07100KL, Package=0402
R2 R3 R4 R5 R6 R7 R8 R9: library part MCD-00481, "Resistor,47R,0402,1%,1/16W", Manufacturer=YAGEO, Manufacturer_Part_Number=RC0402FR-0747RL, Package=R0402
SB1 SB2 SB3 SB4 SB5 SB6 SB8 SB14 SB19 SB20 SB22 SB25 SB27 SB28 SB32 SB35 SB36 SB37 SB38 SB39 SB40 SB43: library part MCD-02162, "Solder Bridge 0402 OFF", Manufacturer=YAGEO, Manufacturer_Part_Number=RC0402JR-070RL, Package=SB0402
SB7 SB9 SB10 SB11 SB12 SB13 SB15 SB16 SB17 SB18 SB21 SB23 SB24 SB26 SB29 SB30 SB31 SB33 SB34 SB41 SB42: library part MCD-01618, "Solder Bridge 0402 ON", Manufacturer=YAGEO, Manufacturer_Part_Number=RC0402JR-070RL, Package=SB0402
SC1 SC2 SC3 SC4 SC5: library part MCD-01587, "shield clip Harwin S0951-46R to fix RF shielded cavity", Manufacturer=HARWIN, Manufacturer_Part_Number=S0951-46R
SH1: library part MCD-03256, Manufacturer=TBD
U1: library part MCD-02743, "MCU, ARM Cortex-M33 32-bit, 1MB Flash, 128KB SRAM, With Crypto, SMPS", Manufacturer=STMICROELECTRONICS, Package=UFQFPN48
X1: library part MCD-02579, "Crystal, 32.768kHz, 6pF, +/-20ppm, 70KR, 1.6x1mm", Manufacturer=NDK, Manufacturer_Part_Number=NX1610SE-32.768KHZ-EXS00A-MU01501, Package=1.6x1mm
X2: library part MCD-02578, "Crystal, 32MHz, 8pF, +/-10ppm, 40R, 1612(metric), T=0.3mm", Manufacturer=NDK, Manufacturer_Part_Number=NX1612SA-32MHZ-EXS00A-CS09166, Package=1612(metric)

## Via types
v1: diameter 0.6, hole 0.3, Top Layer to Bottom Layer, tented both sides, 605 vias
v2: diameter 0.8, hole 0.3, Top Layer to Bottom Layer, tented both sides, 5 vias

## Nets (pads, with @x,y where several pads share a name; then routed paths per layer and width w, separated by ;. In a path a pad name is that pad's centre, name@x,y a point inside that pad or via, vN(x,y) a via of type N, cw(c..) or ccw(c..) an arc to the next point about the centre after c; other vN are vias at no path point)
GND: C1.1 C2.1 C3.1 C4.1 C5.1 C6.2 C7.1 C8.1 C9.1 C10.2 C11.1 C12.1 C13.1 C14.1 C15.2 C16.2 C17.2 C18.2 C19.2 C20.1 C21.2 C22.1 C23.1 C24.2 C25.2 C26.2 C27.1 CN1.1 CN1.6 CN1.7 CN1.14 CN1.17 CN1.22 CN1.25 CN1.28 CN1.31 CN1.34 CN1.37 CN1.40 CN1.46 CN1.49 CN2.2 CN2.8 CN2.14 CN2.20 CN2.26 CN2.32 CN2.38 CN2.44 CN2.50 CN3.5 CN3.7 CN4.2 CN4.3 CN4.4 CN4.5 R1.2 R6.1 SC1.1 SC2.1 SC3.1 SC4.1 SC5.1 U1.1 U1.49 X2.2 X2.4 | length 44.1
  Top Layer w0.2: C11.1@15.545,35.32 C11.1@15.765,35.1 ; C12.1@16.667,35.003 16.692,35.003 16.847,34.848 C12.1@16.847,34.823
  Top Layer w0.45: C11.1@15.545,35.32 16.351,35.32 C12.1@16.667,35.003
  Top Layer w1: 9.185,28.007 9.185,20.745 14.212,20.745 ; 9.21,33.949 9.21,39.718 9.995,39.718 ; 19.749,39.783 20.21,39.783 24.194,39.775 ; 23.432,20.742 31.153,20.742 31.153,26.305 ; 30.137,39.767 31.179,39.767 31.179,35.093
  other v1: 4.894,0.508 6.723,0.508 8.527,0.508 10.228,0.508 11.93,0.508 13.607,0.508 19.017,0.508 20.261,0.508 21.608,0.508 22.776,0.508 24.046,0.508 25.341,0.508 26.978,0.508 28.516,0.508 30.193,0.508 31.916,0.508 34.028,0.508 36.06,0.508 37.61,0.508 39.024,0.508 40.454,0.508 3.04,0.533 15.588,0.533 17.467,0.533 41.521,0.559 1.567,0.584 29.085,1.27 27.707,1.346 42.436,1.337 0.546,1.362 3.497,1.437 5.631,1.473 8.196,1.499 35.628,1.575 10.889,1.618 14.597,1.651 17.264,1.651 12.794,1.676 37.838,1.702 40.607,1.716 5.352,2.327 7.206,2.327 9.593,2.337 11.956,2.362 13.778,2.413 35.349,2.413 15.98,2.464 0.526,2.489 2.507,2.478 4.284,2.478 42.486,2.565 28.034,2.972 10.914,3.226 12.768,3.205 14.602,3.205 17.264,3.205 8.37,3.318 28.897,3.556 4.229,3.634 38.805,3.773 42.467,3.761 0.526,3.81 22.141,4.588 23.03,4.579 30.861,4.578 33.795,4.579 15.521,4.963 13.67,5.046 29.085,5.065 9.513,5.155 10.946,5.158 27.66,5.359 12.286,5.51 14.514,5.896 8.344,6.163 4.331,6.62 42.461,6.655 15.004,6.696 34.455,6.696 28.399,7.03 12.51,7.158 29.908,7.204 39.078,7.509 27.402,7.532 42.461,7.645 8.301,7.777 4.372,7.865 15.172,8.093 28.324,8.221 16.269,9.052 15.038,9.588 8.192,9.719 27.657,9.82 9.034,9.873 13.365,10.1 0.551,10.453 42.461,10.475 28.359,10.567 4.306,10.75 27.136,11.018 33.713,11.244 0.576,11.395 42.461,11.43 9.042,11.7 4.306,11.725 38.494,12.182 14.03,13.264 16.595,13.264 18.256,13.275 26.412,13.275 4.458,13.376 22.88,13.488 38.505,13.58 26.029,13.867 32.271,14.215 0.526,14.3 42.41,14.3 34.678,14.773 38.494,14.776 4.331,14.824 10.956,14.817 0.576,15.189 42.385,15.189 15.424,15.51 4.372,16.45 26.226,16.551 4.356,17.39 8.449,17.42 38.522,17.514 12.972,17.685 0.5,18.085 42.436,18.074 4.331,18.482 38.566,18.589 42.461,19.013 0.526,19.05 22.276,19.124 15.904,19.406 20.513,19.454 8.429,19.52 12.962,19.509 4.382,19.828 25.717,20.28 21.681,20.573 29.858,20.641 17.845,20.813 4.372,21.098 25.951,21.354 8.256,21.538 38.621,21.666 42.436,21.869 4.382,22.266 42.436,22.871 34.678,23.102 38.626,23.107 0.526,23.165 4.382,23.409 24.707,24.086 0.5,24.106 34.678,24.248 4.407,24.476 18.52,24.807 38.6,24.893 17.464,25.414 34.684,25.518 42.461,25.659 17.884,25.979 8.268,26.194 42.436,26.617 18.582,26.747 15.096,27.353 4.407,27.448 4.407,28.286 19.519,28.292 21.45,28.286 22.302,28.286 23.934,28.286 8.42,28.667 20.199,28.69 24.353,28.863 34.732,28.909 19.519,29.128 21.45,29.14 22.302,29.14 0.551,29.464 42.436,29.515 20.199,29.526 28.7,29.547 23.934,29.567 14.546,29.639 19.519,29.964 21.45,29.995 22.302,29.995 4.331,30.013 24.353,30.285 38.82,30.339 20.199,30.362 42.467,30.404 0.5,30.589 16.187,30.678 19.519,30.8 21.45,30.849 22.302,30.849 23.934,30.849 10.926,30.928 8.268,31.233 4.356,31.258 34.488,31.248 10.173,31.334 38.852,31.902 13.514,31.957 8.446,32.071 10.415,32.228 19.83,32.402 21.995,32.402 22.909,32.402 23.822,32.402 34.481,32.528 4.331,32.579 8.42,32.858 11.055,32.884 19.564,33.1 21.554,33.1 22.473,33.1 23.392,33.1 24.311,33.1 28.359,33.112 13.95,33.128 0.5,33.311 42.436,33.341 4.356,33.798 34.405,33.9 13.145,33.976 14.339,33.976 17.039,33.994 18.5,34.249 42.467,34.38 26.178,34.61 0.521,34.733 32.629,34.747 2.1,34.759 39.066,34.759 40.556,34.773 3.163,34.789 4.356,34.789 5.855,34.814 7.684,34.835 14.948,35.424 33.286,35.474 34.506,35.487 18.744,35.64 8.166,35.728 11.9,35.728 10.173,35.754 12.967,35.779 14.059,35.805 42.486,35.832 0.526,35.906 2.71,35.982 4.894,35.982 15.424,35.982 16.939,35.982 37.345,36.016 6.825,36.023 39.083,36.068 11.055,36.186 40.581,36.236 8.349,36.66 17.037,36.694 20.312,36.751 18.56,36.83 13.043,36.957 15.368,37.084 32.142,37.075 0.551,37.135 33.478,37.141 42.477,37.236 10.228,37.27 39.184,37.313 3.878,37.363 5.936,37.363 16.299,37.44 18.495,37.551 20.277,37.719 37.838,37.719 8.349,37.795 13.937,37.795 19.347,37.795 36.715,37.795 11.9,37.821 15.308,37.998 40.632,38.01 21.43,38.092 16.884,38.204 0.551,38.456 19.571,38.711 10.178,38.786 2.735,38.837 39.413,38.837 42.461,38.837 4.869,38.862 6.85,38.862 22.576,38.862 15.283,38.887 11.753,39.065 8.374,39.091 13.962,39.116 16.653,39.218 34.101,39.345 35.882,39.395 37.838,39.395 0.551,39.675 20.211,39.827 15.308,39.878 16.062,39.878 18.82,39.962 40.505,40.437 41.605,40.437 28.823,40.462 38.522,40.462 1.821,40.488 2.659,40.488 4.031,40.488 5.504,40.488 6.85,40.488 8.192,40.488 9.441,40.488 10.66,40.488 30.277,40.488 32.23,40.488 34.308,40.488 36.365,40.488 22.263,40.615 11.498,40.64 19.645,40.64 20.617,40.64 24.071,40.64 26.074,40.64 27.66,40.64 12.184,40.691 13.454,40.716 14.851,40.716 15.978,40.716 42.383,40.705 0.582,40.857 18.745,41.072 1.796,41.445 41.078,41.494 39.235,41.544 33.472,41.621 37.336,41.621 8.858,41.649 3.651,41.674 31.629,41.671 35.493,41.671 6.927,41.699 29.612,41.697 10.501,41.709 19.735,41.709 5.479,41.748 15.309,41.748 26.054,41.748 27.769,41.747 24.211,41.798 42.402,42.157 0.602,42.309 1.822,42.497 41.103,42.545 39.26,42.595 33.498,42.672 37.361,42.672 8.883,42.7 31.655,42.722 35.518,42.722 3.676,42.725 29.637,42.748 6.953,42.751 10.526,42.76 19.761,42.76 5.505,42.799 15.335,42.799 26.08,42.799 27.794,42.799 24.236,42.849 42.393,43.561 0.592,43.713 1.848,43.757 41.129,43.805 39.286,43.855 33.524,43.932 37.387,43.932 8.909,43.96 3.702,43.985 31.681,43.982 35.544,43.982 6.978,44.011 29.663,44.008 10.552,44.021 19.786,44.021 5.531,44.059 15.36,44.059 26.105,44.059 27.82,44.059 24.262,44.109 1.904,44.9 41.186,44.948 39.343,44.998 33.58,45.075 37.444,45.075 8.966,45.103 3.759,45.128 31.737,45.125 35.601,45.125 7.035,45.154 29.72,45.151 42.377,45.161 10.609,45.164 19.843,45.164 5.587,45.202 15.417,45.202 26.162,45.202 27.877,45.202 24.319,45.252 0.576,45.314 1.904,45.916 41.186,45.964 39.343,46.014 33.58,46.091 37.444,46.091 8.966,46.119 3.759,46.144 31.737,46.141 35.601,46.141 7.035,46.17 29.72,46.167 10.609,46.18 19.843,46.18 5.587,46.218 15.417,46.218 26.162,46.218 27.877,46.218 12.628,46.256 13.882,46.256 24.319,46.268 21.65,46.344 22.744,46.344
GPIO2: CN1.8 SB25.2 | length 4
  Bottom Layer w0.2: CN1.8@6.398,29.978 10.298,29.978 10.382,29.895
GPIO3/BOOT0: CN1.9 R1.1 U1.34 | length 27.3
  Top Layer w0.2: v1(10.258,28.751) 10.277,28.77 R1.1@11.125,28.77 ; U1.34@20.145,33.983 20.145,34.854 20.295,35.004 20.295,35.753 20.33,35.789 v1@20.33,35.837
  Bottom Layer w0.2: CN1.9@2.334,28.708 3.991,28.708 4.636,29.353 8.547,29.353 9.157,28.743 10.452,28.743 10.826,29.117 13.261,29.117 13.729,29.586 13.729,29.758 14.233,30.262 15.502,30.262 15.711,30.054 16.434,30.054 17.945,31.565 17.945,35.754 18.463,36.271 19.943,36.271 v1(20.308,35.906)
GPIO5/JTMS/SWDIO: CN1.13 R2.2 U1.27 | length 69.8
  Top Layer w0.2: U1.27@23.645,33.983 23.645,34.417 24.524,35.297 24.838,35.297 25.235,35.694 v1(25.235,36.643)
  Internal 1 w0.21: v1(14.748,23.134) 14.748,21.457 14.466,21.174 14.466,15.027 15.888,13.605 v1(15.888,11.497) ; v1(28.191,22.556) 28.421,22.556 29.934,24.07 29.934,25.238 29.528,25.645 29.528,26.289 30.493,27.254 30.493,35.551 v1(30.061,35.982)
  Bottom Layer w0.2: CN1.13@2.334,26.168 4.067,26.168 4.712,26.813 9.894,26.813 ; v1(25.235,36.643) 25.469,36.877 29.167,36.877 v1(30.061,35.982)
  Bottom Layer w0.21: 9.894,26.813 11.587,26.813 12.349,26.051 12.349,25.716 14.318,23.747 14.318,23.564 v1(14.748,23.134) 14.748,22.822 15.523,22.047 25.164,22.047 25.672,22.556 v1(28.191,22.556) ; v1(15.888,11.497) v1@19.564,11.497 ; R2.2@19.605,10.328 19.605,11.455 v1(19.622,11.471)
GPIO6/JTCK/SWCLK: CN1.15 R3.2 U1.26 | length 70.6
  Top Layer w0.2: U1.26@24.145,33.983 24.145,34.405 24.655,34.916 25.032,34.916 25.926,35.81 v1(25.926,36.236)
  Internal 1 w0.21: v1(13.937,21.885) 13.937,21.552 14.008,21.481 14.008,14.926 15.075,13.859 15.075,10.811 v1(15.101,10.786) ; v1(27.953,35.627) 28.969,35.627 29.655,34.941 29.655,27.6 28.69,26.635 v1@28.69,23.892
  Internal 2 w0.21: v1(15.101,10.786) 16.128,10.786 16.36,11.018 19.046,11.018 19.279,10.786 20.13,10.786 v1(20.811,11.467)
  Bottom Layer w0.2: CN1.15@2.334,24.898 3.991,24.898 4.636,25.543 9.716,25.543 ; v1(25.926,36.236) 26.135,36.236 26.745,35.627 v1(27.953,35.627)
  Bottom Layer w0.21: 9.716,25.543 10.173,26 11.62,26 11.929,25.691 11.929,24.899 12.357,24.47 13.001,24.47 13.935,23.537 13.935,21.689 13.937,21.691 v1(13.937,21.885) 14.267,21.555 25.181,21.555 25.579,21.954 28.544,21.954 28.842,22.252 28.842,23.003 28.639,23.206 v1(28.639,23.945) ; v1(20.811,11.467) 20.887,11.467 R3.2@20.887,10.328
GPIO11: CN1.24 U1.6 | length 23.9
  Top Layer w0.21: U1.6@21.645,27.233 21.645,26.934 22.007,26.572 22.007,25.148 22.683,24.472 22.683,23.65 22.53,23.497 v1(22.53,23.117)
  Internal 1 w0.21: v1(21.857,19.768) 22.263,20.174 22.263,22.232 22.53,22.498 v1(22.53,23.117)
  Bottom Layer w0.2: CN1.24@6.398,19.818 6.654,20.074 20.878,20.074 21.102,19.85 21.775,19.85 v1(21.857,19.768)
GPIO12: CN1.26 U1.7 | length 25.4
  Top Layer w0.2: U1.7@22.145,27.233 22.145,26.936 22.369,26.711 22.369,25.573 v1(22.618,25.324)
  Internal 1 w0.21: v1(19.571,18.085) 19.519,18.137 19.519,23.265 21.577,25.324 v1(22.618,25.324)
  Bottom Layer w0.2: CN1.26@6.398,18.548 6.456,18.491 8.116,18.491 8.635,19.01 8.882,19.01 9.277,19.406 9.853,19.406 10.768,18.491 13.372,18.491 13.51,18.353 19.303,18.353 v1(19.571,18.085)
GPIO14: CN1.29 SB30.1 | length 16.3
  Bottom Layer w0.2: CN1.29@2.334,16.008 3.953,16.008 4.579,15.383 11.553,15.383 13.535,17.364 16.967,17.364 17.231,17.628 17.365,17.762
GPIO15/OSC32_IN: CN1.33 SB37.2 | length 46.5
  Internal 1 w0.21: v1(25.591,15.485) 25.591,18.609 25.972,18.99 26.658,18.99 27.085,19.417 27.085,24.142 27.877,24.933 27.877,27.026 28.366,27.514 28.366,28.845 28.006,29.204 28.006,29.94 28.715,30.648 v1(28.715,31.233)
  Bottom Layer w0.2: CN1.33@2.334,13.468 3.737,13.468 4.382,14.113 8.073,14.113 8.268,13.918 8.268,13.488 8.551,13.205 8.981,13.205 11.221,13.205 12.594,14.578 12.594,15.863 13.631,16.9 17.419,16.9 18.196,16.123 18.75,16.123 19.441,16.815 24.819,16.815 25.591,16.043 v1(25.591,15.485)
  Bottom Layer w0.21: v1(28.715,31.233) 28.817,31.233 29.062,30.987 SB37.2@29.062,30.612
GPIO16/OSC32_OUT: CN1.35 SB38.2 | length 39.3
  Internal 1 w0.21: v1(21.222,14.875) 21.222,16.628 21.857,17.263 v1(21.857,17.9) ; v1(26.15,19.625) 26.708,20.184 26.708,24.349 27.463,25.104 27.463,27.129 27.574,27.24 v1(27.574,27.675)
  Bottom Layer w0.2: CN1.35@2.334,12.198 3.966,12.198 4.61,12.843 11.715,12.843 13.569,14.697 19.861,14.697 20.038,14.875 v1(21.222,14.875)
  Bottom Layer w0.21: v1(21.857,17.9) 25.196,17.9 26.111,18.815 v1@26.111,19.664 ; v1(27.574,27.675) 28.345,27.675 28.802,28.132 28.802,28.459 SB38.2@28.911,28.569
GPIO17: CN1.36 U1.10 | length 34
  Top Layer w0.2: U1.10@23.645,27.233 23.645,26.756 23.905,26.496 23.905,26.312 23.902,26.308 23.979,26.231 23.979,25.721 v1(24.096,25.604)
  Internal 1 w0.21: v1(10.939,11.802) 11.572,12.434 11.572,17.944 11.386,18.13 v1(11.386,19.406) ; v1@23.507,18.964 23.507,21.885 23.787,22.165 23.787,24.476 24.096,24.785 v1(24.096,25.604)
  Bottom Layer w0.2: CN1.36@6.398,12.198 6.42,12.177 8.741,12.177 8.814,12.25 9.316,12.25 9.764,11.802 v1(10.939,11.802)
  Bottom Layer w0.21: v1(11.386,19.406) 11.746,19.406 12.271,18.88 14.315,18.88 14.475,18.72 21.714,18.72 21.885,18.548 23.068,18.548 v1(23.491,18.972)
GPIO18: CN1.38 U1.12 | length 33.6
  Top Layer w0.2: U1.12@24.645,27.233 v1(25.297,26.581)
  Internal 1 w0.21: v1(23.406,14.113) 22.975,14.545 22.975,16.48 24.092,17.598 24.092,18.98 24.092,21.71 25.297,22.915 25.297,24.34 v1(25.297,26.581)
  Bottom Layer w0.2: CN1.38@6.398,10.928 6.637,11.167 8.797,11.167 8.814,11.15 9.27,11.15 9.286,11.167 11.342,11.167 12.101,11.925 12.101,12.657 13.405,13.961 19.393,13.961 21.451,13.961 21.984,14.494 23.025,14.494 v1(23.406,14.113)
GPIO21: CN1.42 SB17.1 SB19.1 | length 4.9
  Bottom Layer w0.2: CN1.42@6.398,8.388 10.375,8.388 ; 10.428,8.381 SB19.1@10.428,9.309
GPIO22: CN1.44 SB9.1 SB14.1 | length 5.3
  Bottom Layer w0.2: CN1.44@6.398,7.118 8.475,7.118 9.316,6.277 10.375,6.277 10.425,6.277 10.384,6.318 SB14.1@10.384,7.205
GPIO23: CN1.45 R9.1 SB21.1 | length 27.6
  Bottom Layer w0.2: CN1.45@2.334,5.848 4.274,5.848 4.925,5.198 8.522,5.198 9.337,4.382 15.987,4.382 16.506,4.901 SB21.1@16.506,5.512 ; SB21.1@16.506,5.603 SB21.1@16.506,5.512 ; R9.1@27.024,4.35 27.024,5.009 25.952,6.081 18.164,6.081 17.596,5.512 SB21.1@16.506,5.512
GPIO24: CN1.47 R8.2 U1.4 | length 54.4
  Top Layer w0.21: U1.4@20.645,27.233 20.645,26.908 21.247,26.305 21.247,24.874 21.476,24.645 21.476,23.621 v1(21.675,23.421)
  Internal 1 w0.21: v1(17.336,4.537) 18.123,5.325 v1(18.123,8.855) 18.177,8.909 18.822,8.909 19.733,9.82 21.119,9.82 21.453,10.154 21.453,12.018 20.351,13.119 20.351,16.678 21.083,17.409 21.083,22.3 21.675,22.893 v1(21.675,23.421)
  Bottom Layer w0.2: CN1.47@2.334,4.578 4.102,4.578 4.728,3.953 16.777,3.953 17.336,4.512 v1(17.336,4.537)
  Bottom Layer w0.21: v1(18.123,8.855) 19.165,7.814 26.353,7.814 26.632,8.093 26.632,10.049 26.353,10.328 R8.2@25.922,10.328
GPIO28: CN2.7 U1.30 | length 26
  Top Layer w0.2: U1.30@22.145,33.983 22.145,34.543 23.025,35.424 23.025,36.211 v1(23,36.211)
  Internal 1 w0.21: v1(34.735,29.988) 35.167,30.42 35.167,37.202 v1(35.167,37.862)
  Bottom Layer w0.2: v1(23,36.211) 23,36.668 24.523,38.191 33.92,38.191 34.249,37.862 v1(35.167,37.862)
  Bottom Layer w0.21: v1(34.735,29.988) 34.744,29.978 CN2.7@36.624,29.978
GPIO29: CN2.9 U1.31 | length 31.9
  Top Layer w0.2: U1.31@21.645,33.983 21.645,34.602 22.289,35.246 22.289,36.795 v1(22.263,36.821)
  Internal 1 w0.21: v1(38.469,38.528) 38.59,38.528 38.469,38.407 38.469,36.589 38.209,36.329 38.209,29.867 v1(38.646,29.429)
  Bottom Layer w0.2: v1(22.263,36.821) 23.984,38.541 34.977,38.541 34.99,38.528 v1(38.469,38.528)
  Bottom Layer w0.21: CN2.9@36.624,28.708 37.926,28.708 v1(38.646,29.429)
